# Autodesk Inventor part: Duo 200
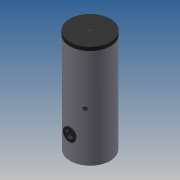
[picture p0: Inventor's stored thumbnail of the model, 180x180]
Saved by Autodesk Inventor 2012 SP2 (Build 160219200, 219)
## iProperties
Created: 2014-05
Part Number: Duo 200
Material: Default
Document SubType Name: Modeling
Designer: michel
Density: 1 g/cm^3
Author: michel
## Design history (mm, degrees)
sketch "Sketch1"
  geometry: C1 r 280 at (0, 0); 1 further point
  constraints: 1 centre point, 1 coincident
  dimensions: "d0" = 560 diameter of C1
extrude "Extrusion1" new body sketch "Sketch1" distance "d1" = 1450; taper "d2" = 0 deg
sketch "Sketch2"
  geometry: L1 (-280, 1450)-(280, 1450) reference; L2 (280, 0)-(280, 1450) reference; L3 (280, 1450)-(280, 1400); L4 (285, 1400)-(285, 1450); L5 (285, 1450)-(280, 1450); L6 (0, -230)-(0, 1380) reference; L7 (285, 1400)-(280, 1400); 1 further point
  constraints: 8 end point, 1 parallel
revolve "Revolution1" sketch "Sketch2" stored, may be unused: angle "d6" = 90 deg
workplane "Work Plane1"
workplane "Work Plane2"
workplane "Work Plane3"
workplane "Work Plane4"
workplane "Work Plane5"
workplane "Work Plane6"
sketch "Sketch3"
  geometry: L1 (404, 1285)-(-394, 1285) reference; L2 (404, 690)-(-394, 690) reference; L3 (404, 885)-(-394, 885) reference; L4 (404, 245)-(-394, 245) reference; L5 (404, 65)-(-394, 65) reference; L6 (280, 0)-(280, 1400) reference; L7 (290, 1285)-(240, 1285); L8 (240, 1285)-(240, 1301.625); L9 (240, 1301.625)-(290, 1301.625); L10 (290, 1301.625)-(290, 1285); L11 (290, 65)-(240, 65); L12 (240, 65)-(240, 81.625); L13 (240, 81.625)-(290, 81.625); L14 (290, 81.625)-(290, 65); L15 (280, 690)-(240, 690); L16 (240, 690)-(240, 700.475); L17 (240, 700.475)-(280, 700.475); L18 (280, 700.475)-(280, 690); L19 (280, 885)-(240, 885); L20 (240, 885)-(240, 901.625); L21 (240, 901.625)-(280, 901.625); L22 (280, 901.625)-(280, 885); L23 (240, 261.625)-(280, 261.625); L24 (280, 261.625)-(280, 245); L25 (280, 245)-(240, 245); L26 (240, 245)-(240, 261.625); 1 further point
  constraints: 40 end point, 8 parallel, 4 point on line, 3 horizontal, 3 perpendicular
  dimensions: "d13" = 50 distance of L8.end L9.end; "d14" = 16.625 distance of L7.end L8.end; "d15" = 50 distance of L12.end L13.end; "d16" = 16.625 distance of L11.end L12.end; "d17" = 40 distance of L16.end L17.end; "d18" = 10.475 distance of L15.end L16.end; "d19" = 40 distance of L20.end L21.end; "d20" = 16.625 distance of L19.end L20.end; "d21" = 40 distance of L23.start L23.end; "d22" = 16.625 distance of L25.end L23.start
revolve "Revolution2" stored, may be unused: angle "d23" = 90 deg
revolve "Revolution3" stored, may be unused: angle "d24" = 90 deg
revolve "Revolution4" stored, may be unused: angle "d25" = 90 deg
revolve "Revolution5" stored, may be unused: angle "d26" = 90 deg
revolve "Revolution6" stored, may be unused: angle "d27" = 90 deg
revolve "Revolution7" stored, may be unused: angle "d28" = 90 deg
revolve "Revolution8" stored, may be unused: angle "d29" = 90 deg
sketch "Sketch4"
  geometry: C1 r 16.625 at (0, 0) reference; C2 r 15.375 at (0, 0); 1 further point
  constraints: 1 centre point, 1 coincident
  dimensions: "d30" = 30.75 diameter of C2
extrude "Extrusion2" cut sketch "Sketch4" distance "d31" = 40; taper "d32" = 0 deg
sketch "Sketch5"
  geometry: C1 r 16.625 at (0, 0) reference; C2 r 15.375 at (0, 0); 1 further point
  constraints: 1 centre point, 1 coincident
  dimensions: "d33" = 30.75 diameter of C2
extrude "Extrusion3" cut sketch "Sketch5" distance "d34" = 40; taper "d35" = 0 deg
workplane "Work Plane7"
sketch "Sketch6"
  geometry: C1 r 9.5 at (0, 0); C2 r 16.625 at (0, 195) reference; C3 r 16.625 at (0, -445) reference; C4 r 15.375 at (0, 195); C5 r 15.375 at (0, -445); 7 further points
  constraints: 6 vertical alignment, 3 centre point, 2 coincident
  dimensions: "d36" = 19 diameter of C1; "d37" = 30.75 diameter of C4; "d38" = 30.75 diameter of C5
  node "Projected Loop1"
  node "Projected Loop2"
extrude "Extrusion4" join sketch "Sketch6" distance "d39" = 40; taper "d40" = 0 deg
extrude "Extrusion5" join sketch "Sketch6" distance "d41" = 40; taper "d42" = 0 deg
extrude "Extrusion6" join sketch "Sketch6" distance "d43" = 40; taper "d44" = 0 deg
workplane "Work Plane8"
workplane "Work Plane9"
sketch "Sketch7"
  geometry: L1 (394.5, 327)-(-407, 327) reference; L2 (-280, 0)-(-280, 1400) reference; L3 (-280, 327)-(-292.5, 327); L4 (-292.5, 327)-(-292.5, 417); L5 (-292.5, 417)-(-280, 417); L6 (-280, 417)-(-280, 327); 1 further point
  constraints: 8 end point, 2 parallel, 2 point on line, 1 horizontal, 1 perpendicular
  dimensions: "d47" = 12.5 distance of L4.end L5.end; "d48" = 90 distance of L3.end L4.end
revolve "Revolution9" sketch "Sketch7" stored, may be unused: angle "d49" = 90 deg
sketch "Sketch8"
  geometry: C1 r 62.5 at (0, 0); A1 r 90 centre (0, 0) between (0, -90) and (0, 90) reference; 1 further point
  constraints: 1 centre point, 1 coincident
  dimensions: "d50" = 125 diameter of C1
extrude "Extrusion7" join sketch "Sketch8" stored distance "d51" = 10; taper "d52" = 0 deg
sketch "Sketch9"
  geometry: C1 r 90 at (0, 0) reference; C2 r 55 at (0, 0); 1 further point
  constraints: 1 centre point, 1 coincident
  dimensions: "d53" = 110 diameter of C2
extrude "Extrusion8" cut sketch "Sketch9" distance "d54" = 50; taper "d55" = 0 deg
sketch "Sketch10"
  geometry: C1 r 285 at (0, 0) reference; C2 r 20.955 at (0, 0); C3 r 19.625 at (0, 0)
  constraints: 2 centre point, 2 coincident
  dimensions: "d56" = 41.91 diameter of C2; "d59" = 39.25 diameter of C3
extrude "Extrusion9" cut sketch "Sketch10" distance "d57" = 50; taper "d58" = 0 deg
extrude "Extrusion10" join sketch "Sketch10" distance "d60" = 50; taper "d61" = 0 deg
workplane "Work Plane10"
sketch "Sketch11"
  geometry: L1 (690, -545.95)-(690, 545.95) reference; L2 (0, 280)-(1400, 280) reference; L3 (690, 280)-(713.9, 280); L4 (713.9, 280)-(713.9, 240); L5 (713.9, 240)-(690, 240); L6 (690, 240)-(690, 280); L7 (667.375, 240)-(667.375, 280); L8 (667.375, 240)-(664.825, 240); L9 (664.825, 240)-(664.825, 280); L10 (667.375, 280)-(664.825, 280); 1 further point
  constraints: 16 end point, 4 perpendicular, 4 point on line, 2 parallel, 1 horizontal
  dimensions: "d63" = 23.9 distance of L4.end L5.end; "d64" = 40 distance of L3.end L4.end; "d67" = 22.625 distance of L5.end L7.start; "d68" = 2.55 distance of L7.start L8.end
revolve "Revolution10" stored, may be unused: angle "d65" = 90 deg
revolve "Revolution11" stored, may be unused: angle "d69" = 90 deg
body "Solid1"
other parameters: "d8" = -65, "d9" = -245, "d12" = 0, "d45" = -327, "d46" = 0, "d62" = 35 deg, "d74" = -885, "d75" = -1285
